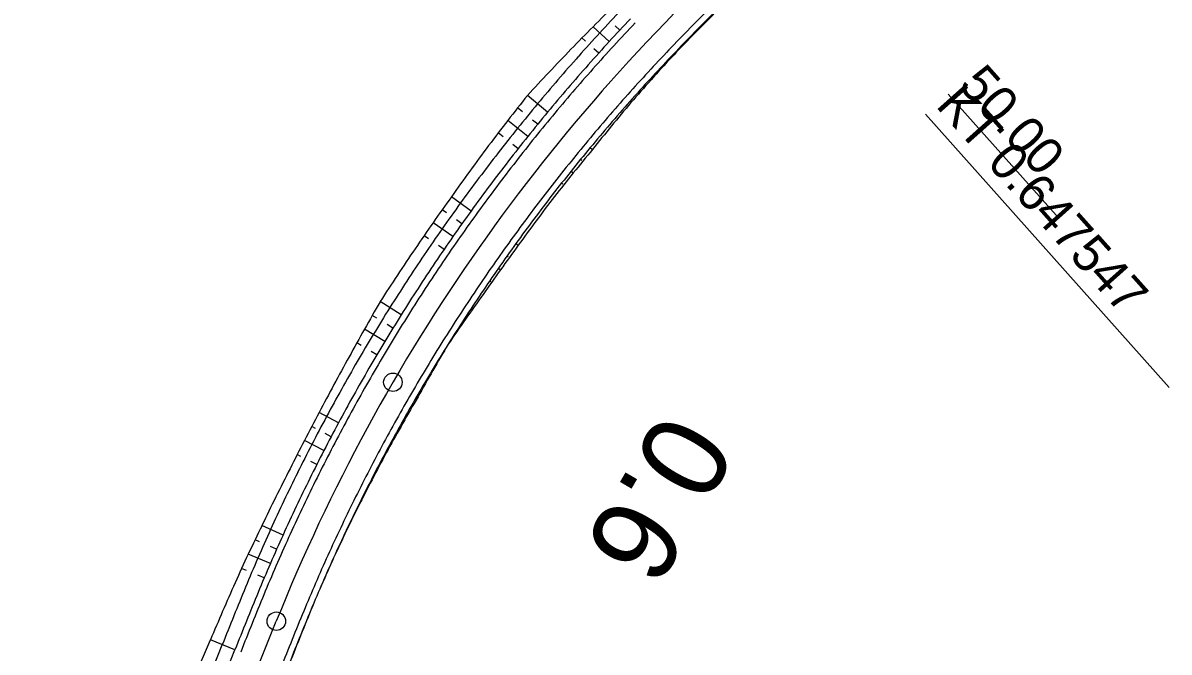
# Model space of a CAD drawing. Extents: x -481656 to -478728, y -1113199 to -1110710.
# Drawn here: x -480212.6 to -480119.6, y -1112558.2 to -1112507.2 of the extents above; entities that cross this region are included whole.
import ezdxf

# ---------------------------------------------------------------- set-up
doc = ezdxf.new("R2010")
doc.units = 0
for name, color, linetype in [('C14_HATCH_SLOPE_L', 7, 'Continuous'), ('C14_HATCH_SLOPE_R', 7, 'Continuous'), ('C14_HECTOMETRY', 7, 'Continuous'), ('C14_HLBODY', 7, 'Continuous'), ('C14_HRANA_TELESO', 7, 'Continuous'), ('C14_KORUNA', 7, 'Continuous'), ('C14_OSA', 7, 'Continuous'), ('C14_PRIKOP', 7, 'Continuous'), ('C14_STANICENI', 7, 'Continuous'), ('C14_VOZOVKA', 7, 'Continuous'), ('C14_ZPEVKRAJ', 7, 'Continuous')]:
    doc.layers.add(name, color=color, linetype=linetype)

msp = doc.modelspace()

# ---------------------------------------------------------------- linework, layer by layer
at = {"layer": 'C14_HATCH_SLOPE_L'}
for p, q in [((-480165.044, -1112508.688), (-480166.356, -1112507.484)), ((-480164.182, -1112507.757), (-480164.562, -1112507.402)), ((-480166.966, -1112508.662), (-480167.259, -1112508.398)), ((-480165.898, -1112509.627), (-480166.286, -1112509.277)), ((-480170.049, -1112514.423), (-480171.684, -1112513.067)), ((-480172.08, -1112514.404), (-480172.485, -1112514.074)), ((-480171.653, -1112516.39), (-480173.277, -1112515.088)), ((-480170.855, -1112515.403), (-480171.266, -1112515.068)), ((-480173.669, -1112516.416), (-480174.06, -1112516.108)), ((-480172.443, -1112517.383), (-480172.86, -1112517.054)), ((-480176.265, -1112522.445), (-480177.855, -1112521.295)), ((-480178.244, -1112522.596), (-480178.606, -1112522.339)), ((-480177.734, -1112524.514), (-480179.347, -1112523.389)), ((-480177.004, -1112523.477), (-480177.443, -1112523.165)), ((-480179.714, -1112524.696), (-480180.079, -1112524.445)), ((-480178.456, -1112525.557), (-480178.902, -1112525.252)), ((-480181.932, -1112530.863), (-480183.632, -1112529.799)), ((-480183.903, -1112531.142), (-480184.277, -1112530.912)), ((-480183.261, -1112533.025), (-480184.913, -1112532.029)), ((-480182.601, -1112531.942), (-480183.065, -1112531.656)), ((-480185.194, -1112533.356), (-480185.539, -1112533.152)), ((-480183.911, -1112534.115), (-480184.38, -1112533.837)), ((-480187.026, -1112539.64), (-480188.591, -1112538.8)), ((-480188.894, -1112540.092), (-480189.195, -1112539.933)), ((-480188.208, -1112541.886), (-480189.789, -1112541.071)), ((-480187.622, -1112540.761), (-480188.107, -1112540.506)), ((-480190.069, -1112542.367), (-480190.374, -1112542.213)), ((-480188.784, -1112543.016), (-480189.274, -1112542.768)), ((-480191.524, -1112548.737), (-480193.231, -1112547.963)), ((-480193.422, -1112549.284), (-480193.791, -1112549.12)), ((-480192.044, -1112549.895), (-480192.548, -1112549.671)), ((-480192.553, -1112551.056), (-480194.342, -1112550.281)), ((-480194.477, -1112551.619), (-480194.883, -1112551.447)), ((-480193.053, -1112552.223), (-480193.562, -1112552.007)), ((-480195.424, -1112558.052), (-480197.419, -1112557.25))]:
    msp.add_line(p, q, dxfattribs=at)
at = {"layer": 'C14_HATCH_SLOPE_R'}
for p, q in [((-480160.049, -1112509.931), (-480159.998, -1112509.979)), ((-480160.893, -1112510.828), (-480160.862, -1112510.857)), ((-480160.83, -1112510.886), (-480160.83, -1112510.886)), ((-480161.729, -1112511.731), (-480161.655, -1112511.799)), ((-480162.558, -1112512.642), (-480162.515, -1112512.68)), ((-480162.472, -1112512.719), (-480162.472, -1112512.719)), ((-480166.586, -1112517.297), (-480166.403, -1112517.448)), ((-480167.368, -1112518.247), (-480167.278, -1112518.321)), ((-480167.187, -1112518.395), (-480167.187, -1112518.395)), ((-480168.142, -1112519.205), (-480167.963, -1112519.348)), ((-480168.909, -1112520.169), (-480168.82, -1112520.238)), ((-480168.731, -1112520.308), (-480168.731, -1112520.308)), ((-480172.618, -1112525.081), (-480172.426, -1112525.22)), ((-480173.335, -1112526.082), (-480173.244, -1112526.146)), ((-480173.153, -1112526.211), (-480173.153, -1112526.211)), ((-480174.044, -1112527.089), (-480173.872, -1112527.209)), ((-480174.744, -1112528.102), (-480174.663, -1112528.158)), ((-480174.582, -1112528.213), (-480174.582, -1112528.213)), ((-480178.118, -1112533.251), (-480178.117, -1112533.251)), ((-480178.767, -1112534.297), (-480178.754, -1112534.304)), ((-480178.742, -1112534.312), (-480178.742, -1112534.312)), ((-480179.407, -1112535.349), (-480179.358, -1112535.378)), ((-480180.038, -1112536.406), (-480180.002, -1112536.428)), ((-480179.965, -1112536.449), (-480179.965, -1112536.449)), ((-480183.061, -1112541.768), (-480182.992, -1112541.805)), ((-480183.639, -1112542.855), (-480183.608, -1112542.872)), ((-480183.577, -1112542.888), (-480183.577, -1112542.888)), ((-480184.208, -1112543.948), (-480184.153, -1112543.976)), ((-480184.767, -1112545.044), (-480184.743, -1112545.056)), ((-480184.72, -1112545.068), (-480184.72, -1112545.068)), ((-480187.426, -1112550.596), (-480187.417, -1112550.6)), ((-480187.93, -1112551.719), (-480187.926, -1112551.722)), ((-480187.921, -1112551.724), (-480187.921, -1112551.724)), ((-480188.425, -1112552.847), (-480188.416, -1112552.851)), ((-480188.91, -1112553.979), (-480188.906, -1112553.98)), ((-480188.902, -1112553.982), (-480188.902, -1112553.982))]:
    msp.add_line(p, q, dxfattribs=at)
at = {"layer": 'C14_HECTOMETRY'}
msp.add_circle((-480182.607, -1112536.339), 0.75, dxfattribs=at)
at = {"layer": 'C14_HLBODY'}
msp.add_line((-480139.367, -1112514.583), (-480119.607, -1112536.756), dxfattribs=at)
msp.add_circle((-480192.068, -1112555.732), 0.75, dxfattribs=at)
at = {"layer": 'C14_HRANA_TELESO'}
msp.add_line((-480199.402, -1112561.842), (-480197.419, -1112557.25), dxfattribs=at)
for centre, radius, start, end in [((-480057.212, -1112616.172), 154.031, 134.16481, 136.07626), ((-480052.61, -1112611.365), 147.686, 134.73676, 136.64662), ((-480057.652, -1112616.948), 154.255, 135.75538, 137.66729), ((-480051.656, -1112610.291), 147.65, 137.20406, 139.11406), ((-480051.27, -1112609.599), 154.331, 141.28188, 143.19201), ((-480050.819, -1112609.186), 147.566, 139.65113, 141.56144), ((-480051.537, -1112609.82), 154.25, 143.06701, 144.97708), ((-480053.154, -1112611.983), 147.52, 140.14636, 142.05622), ((-480053.006, -1112611.824), 154.216, 144.05414, 145.964), ((-480052.619, -1112611.292), 147.521, 142.39574, 144.30561), ((-480053.449, -1112612.513), 154.238, 145.65961, 147.56951), ((-480053.795, -1112612.94), 147.54, 143.51934, 145.42931), ((-480055.924, -1112616.148), 147.658, 143.93555, 145.84671), ((-480050.572, -1112607.686), 154.179, 149.65754, 151.56824), ((-480051.193, -1112608.774), 147.693, 149.24633, 151.15667), ((-480051.763, -1112609.609), 154.064, 150.72827, 152.63834), ((-480053.372, -1112612.519), 147.655, 149.47557, 151.38548), ((-480052.967, -1112611.814), 154.029, 151.7042, 153.61406), ((-480053.341, -1112612.533), 147.689, 151.38654, 153.29644), ((-480054.062, -1112614.085), 154.078, 152.67639, 154.58655), ((-480053.311, -1112612.549), 147.722, 153.29613, 155.20603), ((-480054.738, -1112615.766), 154.199, 153.91455, 155.82524), ((-480052.901, -1112611.696), 147.74, 155.57286, 157.48271), ((-479771.693, -1112738.806), 462.824, 156.27879, 156.90362), ((-479778.643, -1112721.686), 443.225, 157.92555, 158.5688)]:
    msp.add_arc(centre, radius, start, end, dxfattribs=at)
at = {"layer": 'C14_KORUNA'}
msp.add_line((-480197.287, -1112562.691), (-480195.424, -1112558.052), dxfattribs=at)
for centre, radius, start, end in [((-480052.874, -1112611.634), 152.25, 136.50047, 138.41033), ((-480052.874, -1112611.634), 147.75, 134.59061, 136.50047), ((-480052.874, -1112611.634), 152.25, 138.41033, 140.32019), ((-480052.874, -1112611.634), 147.75, 136.50047, 138.41033), ((-480052.874, -1112611.634), 147.75, 138.41033, 140.32019), ((-480052.874, -1112611.634), 152.25, 140.32019, 142.23005), ((-480052.874, -1112611.634), 147.75, 140.32019, 142.23005), ((-480052.874, -1112611.634), 152.25, 142.23005, 144.13991), ((-480052.874, -1112611.634), 147.75, 142.23005, 144.13991), ((-480052.874, -1112611.634), 152.25, 144.13991, 146.04977), ((-480052.874, -1112611.634), 147.75, 144.13991, 146.04976), ((-480052.874, -1112611.634), 152.25, 146.04977, 147.95963), ((-480052.874, -1112611.634), 147.75, 146.04977, 147.95963), ((-480052.874, -1112611.634), 152.25, 147.95963, 149.86949), ((-480052.874, -1112611.634), 147.75, 147.95962, 149.86948), ((-480052.874, -1112611.634), 152.25, 149.86949, 151.77934), ((-480052.874, -1112611.634), 147.75, 149.86948, 151.77934), ((-480052.874, -1112611.634), 152.25, 151.77934, 153.6892), ((-480052.874, -1112611.634), 147.75, 151.77934, 153.6892), ((-480052.874, -1112611.634), 152.25, 153.6892, 155.59906), ((-480052.874, -1112611.634), 147.75, 153.6892, 155.59906), ((-480052.874, -1112611.634), 152.25, 155.59906, 157.50892), ((-480052.874, -1112611.634), 147.75, 155.59906, 157.50892), ((-479770.938, -1112726.671), 456.75, 157.70521, 158.33543), ((-479779.285, -1112723.303), 443.25, 157.70069, 158.34391)]:
    msp.add_arc(centre, radius, start, end, dxfattribs=at)
at = {"layer": 'C14_OSA'}
msp.add_line((-480212.635, -1112606.944), (-480192.068, -1112555.732), dxfattribs=at)
msp.add_arc((-480052.874, -1112611.634), 150, 131.70774, 158.11863, dxfattribs=at)
at = {"layer": 'C14_PRIKOP'}
msp.add_line((-480198.32, -1112562.277), (-480196.453, -1112557.638), dxfattribs=at)
for centre, radius, start, end in [((-480053.067, -1112611.844), 153.292, 136.39406, 138.30392), ((-480053.06, -1112611.85), 153.302, 138.30393, 140.21379), ((-480053.053, -1112611.857), 153.311, 140.21362, 142.12348), ((-480053.044, -1112611.862), 153.321, 142.12383, 144.03369), ((-480053.022, -1112611.846), 153.33, 144.04361, 145.95347), ((-480052.945, -1112611.744), 153.336, 146.00085, 147.91071), ((-480052.928, -1112611.723), 153.34, 147.9208, 149.83066), ((-480052.925, -1112611.726), 153.344, 149.83049, 151.74035), ((-480052.922, -1112611.727), 153.347, 151.74052, 153.65038), ((-480052.918, -1112611.728), 153.35, 153.65038, 155.56024), ((-480052.915, -1112611.73), 153.354, 155.56024, 157.4701), ((-479769.008, -1112727.793), 460.067, 157.66668, 158.29382)]:
    msp.add_arc(centre, radius, start, end, dxfattribs=at)
at = {"layer": 'C14_STANICENI'}
msp.add_line((-480137.536, -1112512.951), (-480128.554, -1112523.03), dxfattribs=at)
at = {"layer": 'C14_VOZOVKA'}
for centre, radius, start, end in [((-480052.874, -1112611.634), 148.25, 134.59061, 136.50047), ((-480052.874, -1112611.634), 151.75, 136.50047, 138.41033), ((-480052.874, -1112611.634), 148.25, 136.50047, 138.41033), ((-480052.874, -1112611.634), 151.75, 138.41033, 140.32019), ((-480052.874, -1112611.634), 148.25, 138.41033, 140.32019), ((-480052.874, -1112611.634), 151.75, 140.32019, 142.23005), ((-480052.874, -1112611.634), 148.25, 140.32019, 142.23005), ((-480052.874, -1112611.634), 151.75, 142.23005, 144.13991), ((-480052.874, -1112611.634), 148.25, 142.23005, 144.13991), ((-480052.874, -1112611.634), 151.75, 144.13991, 146.04977), ((-480052.874, -1112611.634), 148.25, 144.13991, 146.04976), ((-480052.874, -1112611.634), 151.75, 146.04977, 147.95963), ((-480052.874, -1112611.634), 148.25, 146.04977, 147.95963), ((-480052.874, -1112611.634), 151.75, 147.95962, 149.86948), ((-480052.874, -1112611.634), 148.25, 147.95962, 149.86948), ((-480052.874, -1112611.634), 151.75, 149.86949, 151.77934), ((-480052.874, -1112611.634), 148.25, 149.86948, 151.77934), ((-480052.874, -1112611.634), 151.75, 151.77934, 153.6892), ((-480052.874, -1112611.634), 148.25, 151.77934, 153.6892), ((-480052.874, -1112611.634), 151.75, 153.6892, 155.59906), ((-480052.874, -1112611.634), 148.25, 153.6892, 155.59906), ((-480052.874, -1112611.634), 151.75, 155.59906, 157.50892), ((-480052.874, -1112611.634), 148.25, 155.59906, 157.50892), ((-479771.866, -1112726.297), 455.25, 157.70473, 158.33635), ((-479778.357, -1112723.677), 444.75, 157.70121, 158.34295)]:
    msp.add_arc(centre, radius, start, end, dxfattribs=at)
at = {"layer": 'C14_ZPEVKRAJ'}
for centre, radius, start, end in [((-480052.874, -1112611.634), 148.25, 134.59061, 136.50047), ((-480052.874, -1112611.634), 151.75, 136.50047, 138.41033), ((-480052.874, -1112611.634), 148.25, 136.50047, 138.41033), ((-480052.874, -1112611.634), 151.75, 138.41033, 140.32019), ((-480052.874, -1112611.634), 148.25, 138.41033, 140.32019), ((-480052.874, -1112611.634), 151.75, 140.32019, 142.23005), ((-480052.874, -1112611.634), 148.25, 140.32019, 142.23005), ((-480052.874, -1112611.634), 151.75, 142.23005, 144.13991), ((-480052.874, -1112611.634), 148.25, 142.23005, 144.13991), ((-480052.874, -1112611.634), 151.75, 144.13991, 146.04977), ((-480052.874, -1112611.634), 148.25, 144.13991, 146.04976), ((-480052.874, -1112611.634), 151.75, 146.04977, 147.95963), ((-480052.874, -1112611.634), 148.25, 146.04977, 147.95963), ((-480052.874, -1112611.634), 151.75, 147.95962, 149.86948), ((-480052.874, -1112611.634), 148.25, 147.95962, 149.86948), ((-480052.874, -1112611.634), 151.75, 149.86949, 151.77934), ((-480052.874, -1112611.634), 148.25, 149.86948, 151.77934), ((-480052.874, -1112611.634), 151.75, 151.77934, 153.6892), ((-480052.874, -1112611.634), 148.25, 151.77934, 153.6892), ((-480052.874, -1112611.634), 151.75, 153.6892, 155.59906), ((-480052.874, -1112611.634), 148.25, 153.6892, 155.59906), ((-480052.874, -1112611.634), 151.75, 155.59906, 157.50892), ((-480052.874, -1112611.634), 148.25, 155.59906, 157.50892), ((-479771.866, -1112726.297), 455.25, 157.70473, 158.33635), ((-479778.357, -1112723.677), 444.75, 157.70121, 158.34295)]:
    msp.add_arc(centre, radius, start, end, dxfattribs=at)

# ---------------------------------------------------------------- texts
at = {"layer": 'C14_HECTOMETRY'}
msp.add_text('0.6', height=7, rotation=239.82386, dxfattribs=at).set_placement((-480160.681, -1112538.42))
at = {"layer": 'C14_HLBODY'}
msp.add_text('KT 0.647547', height=2.999, rotation=311.70774, dxfattribs=at).set_placement((-480138.621, -1112513.917))
at = {"layer": 'C14_STANICENI'}
msp.add_text('50.00', height=2.999, rotation=311.70774, dxfattribs=at).set_placement((-480136.79, -1112512.285))

doc.saveas('drawing.dxf')
